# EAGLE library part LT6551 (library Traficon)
Quad 3.3V video amplifier RS online: 506-1280
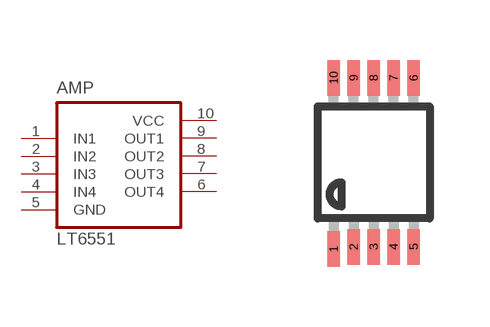
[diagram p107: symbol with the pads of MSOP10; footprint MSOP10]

Designator prefix AMP

## LT6551CMS  [MSOP10]
1  IN1
2  IN2
3  IN3
4  IN4
5  GND
6  OUT4
7  OUT3
8  OUT2
9  OUT1
10  VCC

## Footprint MSOP10 (pad centres in mm)
10-Lead Mini Small Outline Package [MSOP] (RM-10) Source: http://www.analog.com/UploadedFiles/Data_Sheets/35641221898805SSM2167_b.pdf COMPLIANT TO JEDEC STANDARDS MO-187BA
smd 0.305 x 0.889: 1 -1.001,-2.169; 2 -0.5,-2.113; 3 0,-2.113; 4 0.5,-2.113; 5 1,-2.113; 6 1,2.113; 7 0.5,2.113; 8 0,2.113; 9 -0.5,2.113; 10 -1,2.113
